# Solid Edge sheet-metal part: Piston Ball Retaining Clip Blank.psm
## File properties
Title: Piston Ball Retaining Clip
Author: Dan
Template: Normal.psm
Last saved by: Dan
Revision: 25
Application: Solid Edge
Density: 0 kg/mm^3
Accuracy: 0.99
Material Thickness: 1.1 mm
Bend Radius: 3 mm
Relief Width: 3 mm
Relief Length: 3 mm
Neutral Factor: 0.33
Minimum Arc Length: 0.1 mm
Deviational Tolerance: 0.1 mm
Document Number: P52-014
Material: steel
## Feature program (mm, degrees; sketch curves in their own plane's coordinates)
base tab "unnamed BaseTab 1"
sheet metal cutout "unnamed SheetMetalCutout 1"
pattern "unnamed Pattern 1" of "unnamed SheetMetalCutout 1"
pattern "unnamed Pattern 2"
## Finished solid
Body 1: solid body, 14 faces, 36 edges, 24 vertices.
  Faces by surface: plane 8, cylinder 6
  Edges by curve: line 24, circle 12
Bounding box of the edges (mm): 28.497 x 32.660 x 1.100, from (-10.9969, -16.3302, -1.1) to (17.5, 16.3302, 0).
Cylindrical faces by radius (mm): R2.5 x3, R17.5 x3
Planar faces by outward normal: +z 1, -z 1, oblique 6
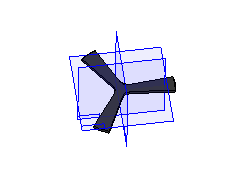
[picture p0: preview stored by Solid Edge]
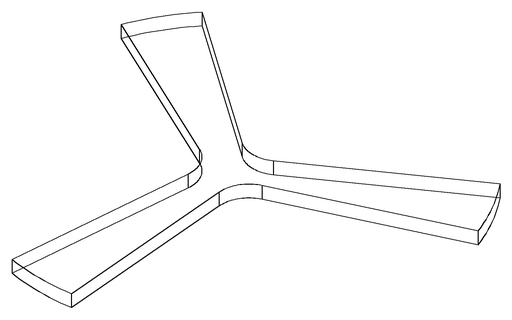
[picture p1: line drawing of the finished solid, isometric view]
